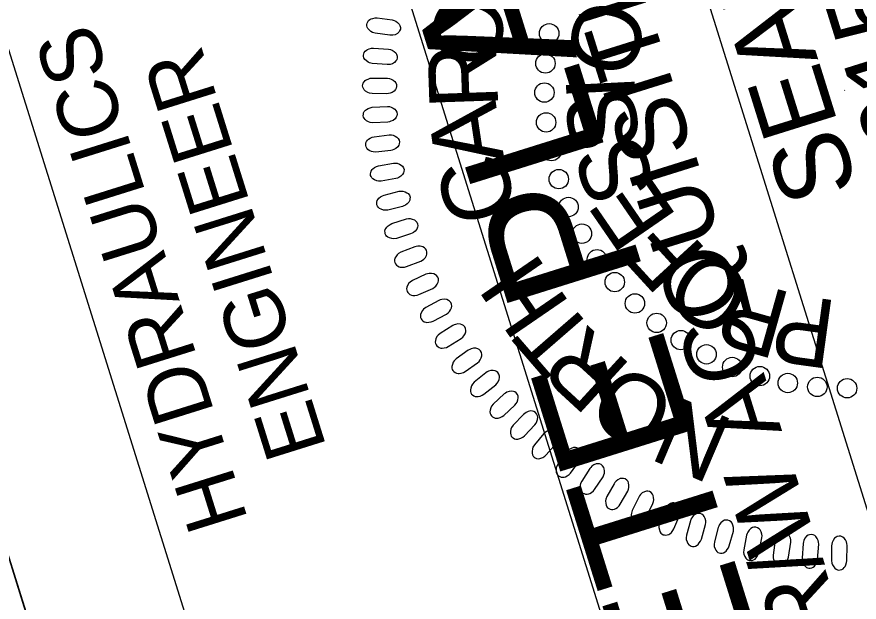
# Model space of a CAD drawing. Extents: x 473667 to 478950, y 494687 to 505998.
# Drawn here: x 473738.2 to 473807.7, y 505601.2 to 505649.4 of the extents above; entities that cross this region are included whole.
import ezdxf

# ---------------------------------------------------------------- set-up
doc = ezdxf.new("R2010")
doc.units = 0
for name, color, linetype in [('Sheet PE Seal Cell', 7, 'Continuous'), ('Sheet Plan CELL', 7, 'Continuous'), ('Sheet Sticker Incomplete CELL', 7, 'Continuous')]:
    doc.layers.add(name, color=color, linetype=linetype)

msp = doc.modelspace()

# ---------------------------------------------------------------- linework, layer by layer
at = {"layer": 'Sheet PE Seal Cell'}
msp.add_line((473806.467, 505643.334), (473806.511, 505643.348), dxfattribs=at)
for points in [[(473768.96, 505647.878), (473767.745, 505648.045), (473767.533, 505648.112), (473767.401, 505648.183), (473767.248, 505648.317), (473767.153, 505648.428), (473767.09, 505648.55), (473767.064, 505648.659), (473767.06, 505648.773), (473767.095, 505648.881), (473767.14, 505648.996), (473767.214, 505649.092), (473767.327, 505649.182), (473767.414, 505649.23), (473767.572, 505649.276), (473767.758, 505649.311), (473767.919, 505649.312), (473769.165, 505649.148), (473769.329, 505649.103), (473769.462, 505649.039), (473769.608, 505648.928), (473769.731, 505648.798), (473769.797, 505648.691), (473769.835, 505648.527), (473769.834, 505648.376), (473769.774, 505648.234), (473769.711, 505648.137), (473769.594, 505648.025), (473769.41, 505647.93), (473769.223, 505647.887), (473769.091, 505647.876)], [(473768.739, 505645.46), (473767.516, 505645.55), (473767.299, 505645.604), (473767.164, 505645.666), (473767.003, 505645.791), (473766.901, 505645.896), (473766.829, 505646.014), (473766.798, 505646.121), (473766.785, 505646.234), (473766.814, 505646.344), (473766.853, 505646.461), (473766.92, 505646.561), (473767.027, 505646.659), (473767.111, 505646.712), (473767.265, 505646.768), (473767.449, 505646.815), (473767.609, 505646.825), (473768.863, 505646.74), (473769.031, 505646.705), (473769.167, 505646.65), (473769.319, 505646.549), (473769.45, 505646.427), (473769.523, 505646.324), (473769.57, 505646.163), (473769.579, 505646.012), (473769.529, 505645.867), (473769.471, 505645.766), (473769.362, 505645.646), (473769.184, 505645.54), (473769.001, 505645.485), (473768.869, 505645.466)], [(473768.72, 505643.061), (473767.493, 505643.075), (473767.274, 505643.115), (473767.136, 505643.169), (473766.967, 505643.282), (473766.859, 505643.381), (473766.78, 505643.494), (473766.741, 505643.599), (473766.722, 505643.711), (473766.744, 505643.823), (473766.775, 505643.943), (473766.836, 505644.047), (473766.936, 505644.15), (473767.017, 505644.209), (473767.167, 505644.275), (473767.347, 505644.332), (473767.507, 505644.353), (473768.764, 505644.347), (473768.933, 505644.323), (473769.073, 505644.276), (473769.231, 505644.185), (473769.369, 505644.071), (473769.448, 505643.973), (473769.506, 505643.815), (473769.524, 505643.665), (473769.483, 505643.517), (473769.432, 505643.413), (473769.331, 505643.287), (473769.16, 505643.169), (473768.98, 505643.103), (473768.85, 505643.075)], [(473768.799, 505640.729), (473767.574, 505640.665), (473767.353, 505640.691), (473767.211, 505640.736), (473767.035, 505640.839), (473766.921, 505640.93), (473766.836, 505641.038), (473766.791, 505641.14), (473766.764, 505641.252), (473766.778, 505641.364), (473766.802, 505641.486), (473766.856, 505641.593), (473766.951, 505641.702), (473767.027, 505641.766), (473767.173, 505641.841), (473767.349, 505641.911), (473767.508, 505641.942), (473768.762, 505642.014), (473768.933, 505642), (473769.074, 505641.962), (473769.238, 505641.881), (473769.384, 505641.776), (473769.469, 505641.684), (473769.536, 505641.53), (473769.564, 505641.382), (473769.532, 505641.231), (473769.487, 505641.124), (473769.395, 505640.991), (473769.231, 505640.863), (473769.056, 505640.787), (473768.928, 505640.75)], [(473769.036, 505638.387), (473767.818, 505638.247), (473767.595, 505638.259), (473767.451, 505638.295), (473767.27, 505638.387), (473767.15, 505638.47), (473767.058, 505638.573), (473767.006, 505638.672), (473766.973, 505638.781), (473766.98, 505638.895), (473766.996, 505639.017), (473767.044, 505639.128), (473767.131, 505639.243), (473767.203, 505639.312), (473767.344, 505639.396), (473767.515, 505639.476), (473767.672, 505639.517), (473768.919, 505639.668), (473769.09, 505639.664), (473769.233, 505639.636), (473769.402, 505639.565), (473769.554, 505639.47), (473769.644, 505639.383), (473769.722, 505639.234), (473769.758, 505639.087), (473769.736, 505638.934), (473769.699, 505638.825), (473769.614, 505638.687), (473769.459, 505638.549), (473769.289, 505638.461), (473769.163, 505638.417)], [(473769.462, 505636.069), (473768.255, 505635.852), (473768.032, 505635.85), (473767.886, 505635.877), (473767.699, 505635.957), (473767.573, 505636.034), (473767.476, 505636.13), (473767.417, 505636.226), (473767.378, 505636.333), (473767.378, 505636.447), (473767.386, 505636.569), (473767.427, 505636.683), (473767.507, 505636.804), (473767.574, 505636.877), (473767.71, 505636.97), (473767.876, 505637.06), (473768.029, 505637.11), (473769.265, 505637.34), (473769.435, 505637.347), (473769.58, 505637.328), (473769.754, 505637.268), (473769.911, 505637.182), (473770.006, 505637.101), (473770.093, 505636.957), (473770.139, 505636.813), (473770.126, 505636.659), (473770.096, 505636.547), (473770.02, 505636.404), (473769.874, 505636.257), (473769.709, 505636.159), (473769.587, 505636.107)], [(473770.001, 505633.762), (473768.81, 505633.47), (473768.588, 505633.454), (473768.44, 505633.472), (473768.248, 505633.54), (473768.119, 505633.608), (473768.014, 505633.698), (473767.951, 505633.791), (473767.905, 505633.895), (473767.898, 505634.008), (473767.898, 505634.132), (473767.931, 505634.248), (473768.003, 505634.373), (473768.066, 505634.45), (473768.196, 505634.551), (473768.356, 505634.652), (473768.505, 505634.712), (473769.724, 505635.018), (473769.894, 505635.037), (473770.04, 505635.026), (473770.217, 505634.977), (473770.379, 505634.902), (473770.48, 505634.826), (473770.575, 505634.688), (473770.631, 505634.547), (473770.627, 505634.393), (473770.603, 505634.279), (473770.537, 505634.132), (473770.401, 505633.976), (473770.243, 505633.867), (473770.123, 505633.808)], [(473770.681, 505631.503), (473769.511, 505631.137), (473769.29, 505631.107), (473769.141, 505631.115), (473768.946, 505631.172), (473768.812, 505631.232), (473768.702, 505631.315), (473768.633, 505631.402), (473768.58, 505631.504), (473768.566, 505631.617), (473768.559, 505631.74), (473768.585, 505631.857), (473768.649, 505631.987), (473768.707, 505632.068), (473768.83, 505632.177), (473768.983, 505632.288), (473769.129, 505632.357), (473770.326, 505632.739), (473770.494, 505632.769), (473770.641, 505632.767), (473770.82, 505632.729), (473770.987, 505632.664), (473771.092, 505632.595), (473771.196, 505632.463), (473771.259, 505632.326), (473771.266, 505632.172), (473771.25, 505632.057), (473771.193, 505631.906), (473771.066, 505631.741), (473770.915, 505631.623), (473770.8, 505631.556)], [(473771.023, 505630.441), (473769.878, 505630.002), (473769.686, 505629.889), (473769.575, 505629.79), (473769.456, 505629.624), (473769.389, 505629.495), (473769.354, 505629.361), (473769.355, 505629.25), (473769.377, 505629.137), (473769.435, 505629.04), (473769.506, 505628.939), (473769.599, 505628.862), (473769.73, 505628.801), (473769.826, 505628.774), (473769.99, 505628.764), (473770.179, 505628.772), (473770.335, 505628.809), (473771.511, 505629.252), (473771.662, 505629.333), (473771.776, 505629.425), (473771.893, 505629.566), (473771.983, 505629.721), (473772.023, 505629.84), (473772.023, 505630.008), (473771.988, 505630.155), (473771.897, 505630.28), (473771.812, 505630.36), (473771.674, 505630.443), (473771.473, 505630.494), (473771.281, 505630.492), (473771.149, 505630.474)], [(473771.946, 505628.175), (473770.83, 505627.665), (473770.646, 505627.54), (473770.541, 505627.434), (473770.433, 505627.262), (473770.374, 505627.128), (473770.348, 505626.993), (473770.355, 505626.881), (473770.384, 505626.77), (473770.449, 505626.677), (473770.525, 505626.581), (473770.623, 505626.51), (473770.758, 505626.456), (473770.855, 505626.435), (473771.019, 505626.436), (473771.207, 505626.457), (473771.362, 505626.503), (473772.507, 505627.018), (473772.652, 505627.109), (473772.761, 505627.208), (473772.869, 505627.356), (473772.949, 505627.516), (473772.981, 505627.638), (473772.97, 505627.805), (473772.926, 505627.95), (473772.828, 505628.069), (473772.739, 505628.143), (473772.595, 505628.218), (473772.392, 505628.256), (473772.2, 505628.242), (473772.07, 505628.215)], [(473773.008, 505626.013), (473771.928, 505625.434), (473771.752, 505625.297), (473771.653, 505625.185), (473771.557, 505625.006), (473771.506, 505624.869), (473771.488, 505624.733), (473771.503, 505624.622), (473771.538, 505624.513), (473771.609, 505624.424), (473771.692, 505624.333), (473771.793, 505624.268), (473771.931, 505624.223), (473772.03, 505624.208), (473772.193, 505624.22), (473772.379, 505624.251), (473772.531, 505624.307), (473773.642, 505624.894), (473773.781, 505624.994), (473773.883, 505625.099), (473773.981, 505625.254), (473774.051, 505625.419), (473774.076, 505625.542), (473774.054, 505625.708), (473774.001, 505625.849), (473773.895, 505625.962), (473773.802, 505626.031), (473773.654, 505626.096), (473773.449, 505626.122), (473773.258, 505626.096), (473773.13, 505626.061)], [(473774.149, 505623.954), (473773.106, 505623.308), (473772.939, 505623.161), (473772.847, 505623.043), (473772.762, 505622.858), (473772.721, 505622.718), (473772.712, 505622.581), (473772.732, 505622.47), (473772.775, 505622.365), (473772.851, 505622.28), (473772.939, 505622.194), (473773.045, 505622.137), (473773.185, 505622.1), (473773.284, 505622.091), (473773.447, 505622.113), (473773.631, 505622.157), (473773.779, 505622.221), (473774.851, 505622.877), (473774.983, 505622.985), (473775.078, 505623.097), (473775.167, 505623.257), (473775.226, 505623.426), (473775.243, 505623.55), (473775.211, 505623.716), (473775.149, 505623.853), (473775.037, 505623.96), (473774.939, 505624.022), (473774.787, 505624.077), (473774.581, 505624.09), (473774.392, 505624.053), (473774.267, 505624.01)], [(473775.438, 505621.913), (473774.438, 505621.203), (473774.281, 505621.046), (473774.197, 505620.922), (473774.124, 505620.733), (473774.09, 505620.59), (473774.09, 505620.452), (473774.118, 505620.343), (473774.167, 505620.241), (473774.248, 505620.16), (473774.342, 505620.081), (473774.451, 505620.03), (473774.593, 505620.002), (473774.693, 505620), (473774.854, 505620.031), (473775.035, 505620.086), (473775.178, 505620.16), (473776.207, 505620.882), (473776.332, 505620.998), (473776.42, 505621.116), (473776.498, 505621.281), (473776.547, 505621.453), (473776.556, 505621.579), (473776.514, 505621.742), (473776.444, 505621.875), (473776.325, 505621.974), (473776.223, 505622.031), (473776.068, 505622.076), (473775.861, 505622.075), (473775.676, 505622.026), (473775.552, 505621.976)], [(473776.875, 505620.057), (473775.921, 505619.285), (473775.775, 505619.118), (473775.699, 505618.99), (473775.637, 505618.796), (473775.613, 505618.651), (473775.622, 505618.514), (473775.657, 505618.408), (473775.712, 505618.308), (473775.798, 505618.233), (473775.896, 505618.159), (473776.009, 505618.115), (473776.152, 505618.096), (473776.252, 505618.101), (473776.41, 505618.142), (473776.588, 505618.209), (473776.725, 505618.291), (473777.707, 505619.076), (473777.825, 505619.2), (473777.905, 505619.323), (473777.973, 505619.493), (473778.011, 505619.668), (473778.012, 505619.794), (473777.96, 505619.954), (473777.881, 505620.082), (473777.756, 505620.173), (473777.651, 505620.223), (473777.494, 505620.259), (473777.287, 505620.246), (473777.105, 505620.185), (473776.985, 505620.127)], [(473778.399, 505618.315), (473777.495, 505617.485), (473777.359, 505617.309), (473777.291, 505617.176), (473777.242, 505616.979), (473777.228, 505616.833), (473777.245, 505616.697), (473777.286, 505616.592), (473777.347, 505616.497), (473777.438, 505616.427), (473777.54, 505616.36), (473777.655, 505616.323), (473777.8, 505616.313), (473777.899, 505616.323), (473778.055, 505616.375), (473778.227, 505616.452), (473778.36, 505616.544), (473779.29, 505617.389), (473779.4, 505617.52), (473779.472, 505617.647), (473779.529, 505617.821), (473779.556, 505617.999), (473779.549, 505618.124), (473779.487, 505618.28), (473779.401, 505618.404), (473779.27, 505618.486), (473779.162, 505618.53), (473779.003, 505618.556), (473778.798, 505618.53), (473778.62, 505618.458), (473778.504, 505618.392)], [(473779.989, 505616.631), (473779.139, 505615.745), (473779.014, 505615.561), (473778.955, 505615.425), (473778.919, 505615.224), (473778.913, 505615.078), (473778.938, 505614.943), (473778.986, 505614.842), (473779.054, 505614.749), (473779.148, 505614.686), (473779.255, 505614.625), (473779.372, 505614.595), (473779.517, 505614.595), (473779.615, 505614.611), (473779.767, 505614.672), (473779.935, 505614.761), (473780.062, 505614.86), (473780.937, 505615.762), (473781.038, 505615.899), (473781.102, 505616.031), (473781.148, 505616.208), (473781.164, 505616.387), (473781.149, 505616.512), (473781.077, 505616.664), (473780.983, 505616.781), (473780.848, 505616.856), (473780.738, 505616.893), (473780.577, 505616.909), (473780.374, 505616.869), (473780.2, 505616.787), (473780.089, 505616.714)], [(473781.682, 505615.047), (473780.89, 505614.11), (473780.776, 505613.918), (473780.726, 505613.778), (473780.702, 505613.576), (473780.705, 505613.43), (473780.739, 505613.297), (473780.794, 505613.198), (473780.867, 505613.111), (473780.965, 505613.053), (473781.075, 505612.999), (473781.194, 505612.977), (473781.338, 505612.986), (473781.436, 505613.008), (473781.584, 505613.079), (473781.745, 505613.178), (473781.866, 505613.285), (473782.683, 505614.24), (473782.775, 505614.383), (473782.831, 505614.519), (473782.865, 505614.699), (473782.87, 505614.877), (473782.848, 505615.001), (473782.766, 505615.148), (473782.665, 505615.26), (473782.525, 505615.326), (473782.413, 505615.356), (473782.251, 505615.362), (473782.051, 505615.309), (473781.883, 505615.215), (473781.777, 505615.136)], [(473783.572, 505613.543), (473782.841, 505612.558), (473782.74, 505612.36), (473782.698, 505612.217), (473782.687, 505612.013), (473782.7, 505611.867), (473782.742, 505611.737), (473782.802, 505611.642), (473782.881, 505611.559), (473782.982, 505611.508), (473783.096, 505611.461), (473783.215, 505611.446), (473783.359, 505611.464), (473783.455, 505611.492), (473783.598, 505611.573), (473783.753, 505611.681), (473783.866, 505611.795), (473784.622, 505612.799), (473784.705, 505612.949), (473784.753, 505613.088), (473784.776, 505613.269), (473784.769, 505613.448), (473784.739, 505613.57), (473784.648, 505613.712), (473784.54, 505613.817), (473784.397, 505613.874), (473784.283, 505613.896), (473784.121, 505613.893), (473783.924, 505613.828), (473783.763, 505613.724), (473783.662, 505613.637)], [(473785.46, 505612.163), (473784.792, 505611.135), (473784.704, 505610.931), (473784.671, 505610.785), (473784.673, 505610.582), (473784.694, 505610.437), (473784.745, 505610.309), (473784.811, 505610.219), (473784.894, 505610.141), (473784.999, 505610.096), (473785.116, 505610.056), (473785.236, 505610.049), (473785.378, 505610.076), (473785.472, 505610.11), (473785.61, 505610.199), (473785.758, 505610.316), (473785.864, 505610.439), (473786.555, 505611.487), (473786.628, 505611.642), (473786.667, 505611.784), (473786.678, 505611.966), (473786.66, 505612.144), (473786.622, 505612.264), (473786.523, 505612.4), (473786.409, 505612.498), (473786.262, 505612.546), (473786.147, 505612.561), (473785.986, 505612.547), (473785.794, 505612.47), (473785.64, 505612.356), (473785.543, 505612.264)], [(473787.463, 505610.917), (473786.86, 505609.849), (473786.785, 505609.64), (473786.762, 505609.492), (473786.776, 505609.289), (473786.807, 505609.146), (473786.865, 505609.022), (473786.937, 505608.935), (473787.025, 505608.863), (473787.133, 505608.825), (473787.252, 505608.793), (473787.372, 505608.793), (473787.512, 505608.829), (473787.604, 505608.868), (473787.736, 505608.966), (473787.876, 505609.093), (473787.973, 505609.22), (473788.598, 505610.312), (473788.662, 505610.47), (473788.691, 505610.614), (473788.691, 505610.797), (473788.662, 505610.974), (473788.617, 505611.091), (473788.509, 505611.22), (473788.388, 505611.311), (473788.239, 505611.349), (473788.123, 505611.358), (473787.964, 505611.334), (473787.776, 505611.245), (473787.629, 505611.121), (473787.54, 505611.023)], [(473789.496, 505609.812), (473788.962, 505608.708), (473788.9, 505608.494), (473788.886, 505608.346), (473788.913, 505608.144), (473788.952, 505608.003), (473789.019, 505607.883), (473789.095, 505607.801), (473789.188, 505607.734), (473789.297, 505607.704), (473789.418, 505607.679), (473789.538, 505607.686), (473789.676, 505607.73), (473789.765, 505607.776), (473789.891, 505607.881), (473790.022, 505608.017), (473790.113, 505608.151), (473790.666, 505609.279), (473790.72, 505609.441), (473790.741, 505609.587), (473790.729, 505609.77), (473790.689, 505609.944), (473790.636, 505610.058), (473790.521, 505610.18), (473790.395, 505610.263), (473790.243, 505610.292), (473790.128, 505610.293), (473789.969, 505610.259), (473789.788, 505610.158), (473789.649, 505610.026), (473789.566, 505609.922)], [(473791.683, 505608.807), (473791.219, 505607.672), (473791.171, 505607.454), (473791.166, 505607.305), (473791.206, 505607.106), (473791.255, 505606.967), (473791.328, 505606.852), (473791.41, 505606.775), (473791.507, 505606.714), (473791.618, 505606.69), (473791.74, 505606.673), (473791.859, 505606.688), (473791.994, 505606.741), (473792.079, 505606.792), (473792.198, 505606.905), (473792.322, 505607.049), (473792.403, 505607.188), (473792.885, 505608.348), (473792.928, 505608.514), (473792.939, 505608.66), (473792.917, 505608.842), (473792.866, 505609.013), (473792.805, 505609.124), (473792.683, 505609.239), (473792.553, 505609.313), (473792.399, 505609.333), (473792.283, 505609.327), (473792.128, 505609.283), (473791.953, 505609.171), (473791.823, 505609.03), (473791.746, 505608.921)], [(473793.763, 505607.861), (473793.436, 505606.679), (473793.414, 505606.457), (473793.427, 505606.309), (473793.489, 505606.115), (473793.554, 505605.984), (473793.641, 505605.877), (473793.731, 505605.811), (473793.834, 505605.762), (473793.947, 505605.751), (473794.07, 505605.748), (473794.187, 505605.777), (473794.315, 505605.846), (473794.394, 505605.907), (473794.498, 505606.033), (473794.604, 505606.19), (473794.668, 505606.338), (473795.011, 505607.547), (473795.034, 505607.716), (473795.028, 505607.863), (473794.984, 505608.041), (473794.913, 505608.205), (473794.841, 505608.308), (473794.705, 505608.407), (473794.567, 505608.466), (473794.412, 505608.468), (473794.298, 505608.448), (473794.149, 505608.386), (473793.989, 505608.254), (473793.876, 505608.099), (473793.813, 505607.982)], [(473796.057, 505607.307), (473795.739, 505606.122), (473795.718, 505605.901), (473795.732, 505605.752), (473795.796, 505605.559), (473795.862, 505605.428), (473795.949, 505605.322), (473796.04, 505605.256), (473796.144, 505605.208), (473796.257, 505605.198), (473796.38, 505605.196), (473796.497, 505605.227), (473796.624, 505605.296), (473796.702, 505605.357), (473796.806, 505605.485), (473796.91, 505605.642), (473796.973, 505605.791), (473797.306, 505607.003), (473797.328, 505607.172), (473797.321, 505607.319), (473797.276, 505607.496), (473797.204, 505607.66), (473797.131, 505607.762), (473796.994, 505607.86), (473796.855, 505607.918), (473796.701, 505607.919), (473796.587, 505607.898), (473796.438, 505607.834), (473796.279, 505607.702), (473796.167, 505607.546), (473796.104, 505607.428)], [(473798.402, 505606.676), (473798.159, 505605.473), (473798.152, 505605.251), (473798.175, 505605.103), (473798.252, 505604.915), (473798.326, 505604.788), (473798.419, 505604.688), (473798.514, 505604.628), (473798.62, 505604.586), (473798.734, 505604.584), (473798.857, 505604.589), (473798.972, 505604.627), (473799.094, 505604.704), (473799.168, 505604.77), (473799.264, 505604.904), (473799.358, 505605.068), (473799.412, 505605.22), (473799.668, 505606.45), (473799.68, 505606.62), (473799.663, 505606.766), (473799.607, 505606.94), (473799.525, 505607.1), (473799.445, 505607.197), (473799.303, 505607.287), (473799.16, 505607.336), (473799.006, 505607.326), (473798.894, 505607.299), (473798.749, 505607.226), (473798.599, 505607.083), (473798.497, 505606.921), (473798.442, 505606.8)], [(473800.76, 505606.252), (473800.593, 505605.037), (473800.6, 505604.815), (473800.633, 505604.669), (473800.721, 505604.486), (473800.802, 505604.364), (473800.903, 505604.27), (473801.001, 505604.216), (473801.109, 505604.181), (473801.223, 505604.185), (473801.346, 505604.199), (473801.457, 505604.244), (473801.574, 505604.328), (473801.644, 505604.399), (473801.732, 505604.538), (473801.816, 505604.708), (473801.86, 505604.863), (473802.038, 505606.108), (473802.039, 505606.278), (473802.013, 505606.422), (473801.946, 505606.593), (473801.854, 505606.746), (473801.769, 505606.838), (473801.621, 505606.92), (473801.476, 505606.959), (473801.322, 505606.94), (473801.212, 505606.905), (473801.072, 505606.824), (473800.931, 505606.672), (473800.84, 505606.503), (473800.793, 505606.378)], [(473803.063, 505605.989), (473802.973, 505604.766), (473802.994, 505604.545), (473803.035, 505604.401), (473803.135, 505604.224), (473803.224, 505604.107), (473803.33, 505604.02), (473803.431, 505603.973), (473803.542, 505603.944), (473803.655, 505603.956), (473803.776, 505603.977), (473803.885, 505604.028), (473803.996, 505604.12), (473804.062, 505604.196), (473804.14, 505604.34), (473804.213, 505604.515), (473804.247, 505604.672), (473804.347, 505605.924), (473804.337, 505606.095), (473804.303, 505606.238), (473804.225, 505606.403), (473804.124, 505606.551), (473804.033, 505606.638), (473803.88, 505606.71), (473803.733, 505606.74), (473803.581, 505606.711), (473803.473, 505606.669), (473803.339, 505606.579), (473803.207, 505606.419), (473803.127, 505606.244), (473803.087, 505606.117)], [(473805.414, 505605.808), (473805.401, 505604.582), (473805.436, 505604.362), (473805.486, 505604.221), (473805.596, 505604.05), (473805.693, 505603.94), (473805.804, 505603.859), (473805.907, 505603.818), (473806.02, 505603.797), (473806.132, 505603.816), (473806.252, 505603.844), (473806.357, 505603.903), (473806.463, 505604.001), (473806.524, 505604.081), (473806.593, 505604.23), (473806.654, 505604.408), (473806.679, 505604.568), (473806.7, 505605.824), (473806.679, 505605.994), (473806.636, 505606.134), (473806.548, 505606.294), (473806.437, 505606.435), (473806.341, 505606.517), (473806.185, 505606.578), (473806.035, 505606.599), (473805.885, 505606.561), (473805.781, 505606.512), (473805.652, 505606.414), (473805.531, 505606.246), (473805.461, 505606.067), (473805.43, 505605.937)]]:
    msp.add_lwpolyline(points, close=True, dxfattribs=at)
for centre in [(473782.11, 505648.037), (473781.799, 505645.562), (473781.717, 505643.158), (473781.86, 505640.7), (473782.307, 505638.337), (473782.906, 505636.021), (473783.708, 505633.727), (473784.813, 505631.529), (473786.059, 505629.415), (473787.523, 505627.537), (473789.186, 505625.779), (473790.982, 505624.172), (473792.972, 505622.751), (473795.092, 505621.579), (473797.214, 505620.532), (473799.493, 505619.785), (473801.801, 505619.214), (473804.239, 505618.893), (473806.694, 505618.785)]:
    msp.add_circle(centre, 0.801, dxfattribs=at)
at = {"layer": 'Sheet Plan CELL'}
msp.add_line((473777.447, 505477.469), (473717.621, 505668.351), dxfattribs=at)
msp.add_line((473777.447, 505477.469), (473717.621, 505668.351), dxfattribs=at)
for points in [[(473759.453, 505576.677), (473729.55, 505672.088), (473836.913, 505705.736), (473866.82, 505610.313)], [(473753.507, 505469.969), (473693.706, 505660.898), (473717.621, 505668.351), (473777.447, 505477.469)]]:
    msp.add_lwpolyline(points, close=True, dxfattribs=at)
at = {"layer": 'Sheet Sticker Incomplete CELL'}
msp.add_lwpolyline([(473835.104, 505523.354), (473812.679, 505516.329), (473768.733, 505656.606), (473791.158, 505663.632)], close=True, dxfattribs=at)

# ---------------------------------------------------------------- texts
at = {"layer": 'Sheet PE Seal Cell'}
for s, height, rotation, p in [('46155', 6.2363, 107.37612, (473816.048, 505635.447)), ('SEAL', 6.2363, 107.37612, (473807.637, 505635.273)), ('O', 5.669, 79.02501, (473777.653, 505644.912)), ('O', 5.669, 76.9246, (473788.94, 505644.137)), ('R', 5.669, 92.00372, (473777.913, 505641.897)), ('I', 5.669, 92.80419, (473789.225, 505642.651)), ('S', 5.669, 100.74399, (473789.759, 505638.836)), ('A', 5.669, 98.49308, (473778.412, 505637.645)), ('S', 5.669, 108.68379, (473791.01, 505635.182)), ('C', 5.669, 104.98244, (473779.581, 505633.217)), ('E', 5.669, 124.56338, (473792.753, 505632.828)), ('F', 5.669, 132.50318, (473795.234, 505630.053)), ('H', 5.669, 124.45051, (473783.921, 505625.664)), ('O', 5.669, 148.38278, (473799.335, 505627.463)), ('R', 5.669, 164.26237, (473802.277, 505626.589)), ('P', 5.669, 172.20217, (473805.989, 505625.984)), ('T', 5.669, 130.93986, (473786.217, 505623.052)), ('R', 5.669, 137.42922, (473789.011, 505620.552)), ('O', 5.669, 150.40793, (473792.94, 505618.141)), ('N', 5.669, 156.89729, (473797.524, 505616.07))]:
    msp.add_text(s, height=height, rotation=rotation, dxfattribs=at).set_placement(p)
at = {"layer": 'Sheet Plan CELL'}
for s, p in [('HYDRAULICS', (473757.289, 505607.921)), ('ENGINEER', (473763.762, 505613.892))]:
    msp.add_text(s, height=5.0001, rotation=107.39476, dxfattribs=at).set_placement(p)
at = {"layer": 'Sheet Sticker Incomplete CELL'}
for s, height, p in [('INCOMPLETE PLANS', 11.52, (473821.263, 505528.397)), ('DO NOT USE FOR R/W ACQUISITION', 5.76, (473826.924, 505533.576))]:
    msp.add_text(s, height=height, rotation=107.39476, dxfattribs=at).set_placement(p)

doc.saveas('drawing.dxf')
